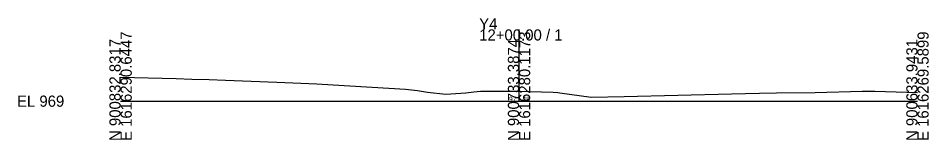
# Model space of a CAD drawing. Extents: x -26 to 2603, y -10 to 522.
# Drawn here: x 2374.3 to 2602.8, y -9.7 to 20.8 of the extents above; entities that cross this region are included whole.
import ezdxf

# ---------------------------------------------------------------- set-up
doc = ezdxf.new("R2010")
doc.units = 0
for name, color, linetype in [('Exist Cross Section Cell', 7, 'Continuous'), ('Exist XS Center Line Elevation Label', 7, 'Continuous'), ('Exist XS Ground Line', 7, 'Continuous')]:
    doc.layers.add(name, color=color, linetype=linetype)

msp = doc.modelspace()

# ---------------------------------------------------------------- linework, layer by layer
at = {"layer": 'Exist Cross Section Cell'}
for p, q in [((2500, 0), (2500, 18.01)), ((2400, 0), (2500, 0)), ((2500, 0), (2600, 0))]:
    msp.add_line(p, q, dxfattribs=at)
at = {"layer": 'Exist XS Ground Line'}
for p, q in [((2400, 6), (2413.91, 5.68)), ((2413.91, 5.68), (2417.9, 5.55)), ((2417.9, 5.55), (2422.24, 5.44)), ((2422.24, 5.44), (2426.34, 5.25)), ((2426.34, 5.25), (2439.19, 4.73)), ((2439.19, 4.73), (2449.28, 4.31)), ((2449.28, 4.31), (2453.34, 4.13)), ((2453.34, 4.13), (2471.48, 2.97)), ((2471.48, 2.97), (2474.48, 2.69)), ((2474.48, 2.69), (2476.99, 2.22)), ((2486.67, 2.08), (2488.62, 2.31)), ((2488.62, 2.31), (2490.35, 2.48)), ((2490.35, 2.48), (2492.65, 2.48)), ((2492.65, 2.48), (2499.87, 2.49)), ((2499.87, 2.49), (2508.55, 2.22)), ((2574.31, 2.2), (2586.09, 2.48)), ((2586.09, 2.48), (2587.44, 2.5)), ((2587.44, 2.5), (2589.34, 2.48)), ((2589.34, 2.48), (2600, 2.15)), ((2476.99, 2.22), (2481.65, 1.74)), ((2481.65, 1.74), (2486.67, 2.08)), ((2508.55, 2.22), (2509.71, 2.18)), ((2509.71, 2.18), (2510.24, 2.11)), ((2510.24, 2.11), (2518.1, 1.04)), ((2518.1, 1.04), (2526.39, 1.17)), ((2526.39, 1.17), (2553.34, 1.85)), ((2553.34, 1.85), (2560.32, 2.02)), ((2560.32, 2.02), (2564.6, 2.09)), ((2564.6, 2.09), (2574.31, 2.2))]:
    msp.add_line(p, q, dxfattribs=at)

# ---------------------------------------------------------------- texts
at = {"layer": 'Exist Cross Section Cell'}
for s, p in [('Y4', (2490, 18.01)), ('12+00.00 / 1', (2490, 15.21)), ('EL 969', (2374, -1.4))]:
    msp.add_text(s, height=2.8, dxfattribs=at).set_placement(p)
for s, p in [('E 1616290.6447', (2402.8, -10)), ('E 1616280.1173', (2502.8, -10)), ('E 1616269.5899', (2602.8, -10)), ('N 900832.8317', (2400, -10)), ('N 900733.3874', (2500, -10)), ('N 900633.9431', (2600, -10))]:
    msp.add_text(s, height=2.8, rotation=90, dxfattribs=at).set_placement(p)
at = {"layer": 'Exist XS Center Line Elevation Label'}
msp.add_text('971.48', height=1.25, dxfattribs=at).set_placement((2497.45, -0.14))

doc.saveas('drawing.dxf')
